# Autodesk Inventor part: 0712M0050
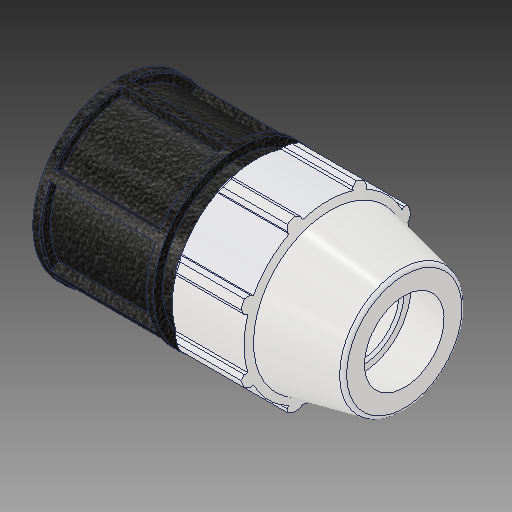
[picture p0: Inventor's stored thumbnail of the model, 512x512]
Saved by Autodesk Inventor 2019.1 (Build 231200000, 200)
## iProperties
Created: 2017-02
Part Number: 0712M0050
Material: PVC-Piping
Description: PLASSON END PLUG 1/2''
Document SubType Name: Modeling
Designer: KIM
Mass: 92.6774 g
Surface Area: 199.44 cm^2
Volume: 66.1981 cm^3
Density: 1.4 g/cm^3
Appearance: PTFE
Author: Кирилл
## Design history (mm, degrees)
derived "0712M0.ipt"
feature "Solid1::0712M0.ipt"
tag "TaggingFeature1"
body "Solid1"
other parameters: "d2" = 21.2, "d4" = 11.28486, "d5" = 19.7485, "d7" = 48.006, "d8" = 40.8051, "d9" = 11.28486, "d11" = 2.25697, "d12" = 40.8051, "d13" = 120 deg, "d15" = 12 deg, "d16" = 45.6057, "d18" = 1.06, "d19" = 35 deg, "d20" = 17.5 deg, "d21" = 44.64558, "d23" = 0, "d25" = 360 deg, "d27" = 0.96012, "d34" = 2.4003, "d36" = 0, "d42" = 19.7485, "d43" = 1.44018, "d46" = 0.636, "d53" = 0.424, "d55" = 360 deg, "d59" = 27.6479, "d64" = 78.994, "d66" = 4.8006, "d67" = 2.4003, "d68" = 73.914, "d70" = 40.8051, "d_" = 21.2, "E_" = 48.006, "H_" = 78.994, "l_" = 73.914
